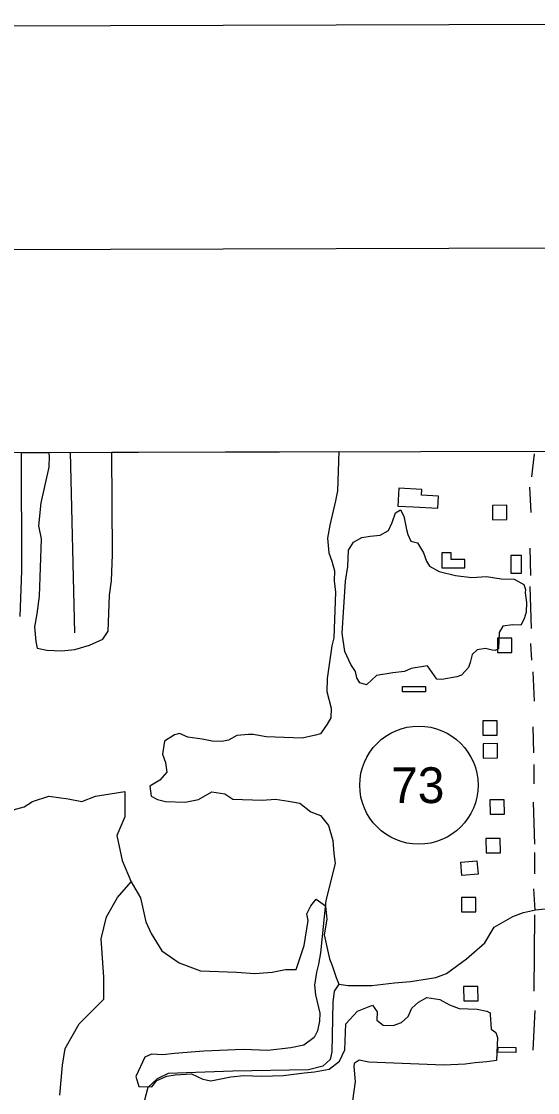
# Model space of a CAD drawing. Extents: x 3355677 to 3393573, y 612928 to 638357.
# Drawn here: x 3388107 to 3389547, y 634782 to 637774 of the extents above; entities that cross this region are included whole.
import ezdxf

# ---------------------------------------------------------------- set-up
doc = ezdxf.new("R2010")
doc.units = 0
for name, color, linetype in [('G-ANNO-NPLT', 7, 'Continuous'), ('V-ANNO-SYMB', 7, 'Continuous'), ('V-BLDG-OTLN', 7, 'Continuous'), ('V-GRID-FRAM', 7, 'Continuous'), ('V-ROAD-IDEN', 7, 'Continuous'), ('V-SITE-VEGE', 7, 'Continuous'), ('V-TOPO-SHOR', 7, 'Continuous')]:
    doc.layers.add(name, color=color, linetype=linetype)

msp = doc.modelspace()

# ---------------------------------------------------------------- linework, layer by layer
at = {"layer": 'G-ANNO-NPLT'}
msp.add_lwpolyline([(3356323.2, 613511.2), (3392989.8, 613607.2), (3392926.5, 637773.8), (3356260, 637677.8)], close=True, dxfattribs=at)
at = {"layer": 'V-ANNO-SYMB'}
msp.add_lwpolyline([(3359071.7, 614143.5), (3392154.8, 614230.1), (3392094.8, 637146.6), (3359011.7, 637060), (3359071.7, 614143.5)], dxfattribs=at)
at = {"layer": 'V-BLDG-OTLN'}
for points in [[(3389200.9, 636417.8), (3389268.8, 636414), (3389270.7, 636448), (3389223.3, 636450.7), (3389224.2, 636466.6), (3389159.9, 636470.1), (3389157.1, 636420.2)], [(3389461.6, 636382.4), (3389461.1, 636422.4), (3389421.1, 636421.9), (3389421.6, 636381.9)], [(3389280.1, 636289.5), (3389280.1, 636248.1), (3389344.3, 636248.1), (3389344.3, 636270.7), (3389306.5, 636270.7), (3389306.5, 636289.5)], [(3389472.5, 636282), (3389472.5, 636233), (3389502.7, 636233), (3389502.7, 636282)], [(3389475.6, 636011.3), (3389475.1, 636051.3), (3389435.1, 636050.8), (3389435.6, 636010.8)], [(3389170.8, 635916.2), (3389234.9, 635916.2), (3389234.9, 635901.1), (3389170.8, 635901.1)], [(3389434.9, 635780.4), (3389434.4, 635820.4), (3389394.4, 635819.9), (3389394.9, 635779.9)], [(3389435.6, 635716.6), (3389435.1, 635756.6), (3389395.1, 635756.1), (3389395.6, 635716.1)], [(3389454.7, 635559.9), (3389454.2, 635599.9), (3389414.2, 635599.4), (3389414.7, 635559.4)], [(3389443.5, 635452.1), (3389443, 635492.1), (3389403, 635491.6), (3389403.5, 635451.6)], [(3389332.9, 635425.9), (3389378.2, 635429.7), (3389381.3, 635392.5), (3389336, 635388.8)], [(3389375.1, 635287.1), (3389374.6, 635327), (3389334.6, 635326.5), (3389335.1, 635286.5)], [(3389381.1, 635038.4), (3389380.6, 635078.4), (3389340.6, 635077.9), (3389341.1, 635037.9)], [(3389486.7, 634894.3), (3389436.7, 634895), (3389436.9, 634909), (3389486.9, 634908.3)]]:
    msp.add_lwpolyline(points, close=True, dxfattribs=at)
at = {"layer": 'V-GRID-FRAM'}
msp.add_lwpolyline([(3359767.9, 636495.9), (3391341.6, 636578.5), (3391397.2, 618394.8), (3359807.6, 618312.1), (3359767.9, 636495.9)], dxfattribs=at)
at = {"layer": 'V-ROAD-IDEN'}
msp.add_circle((3389216.1, 635640.6), 165, dxfattribs=at)
at = {"layer": 'V-SITE-VEGE'}
for p, q in [((3388107.6, 636570.1), (3388182.9, 636570.2)), ((3388108.7, 636239.2), (3388107.6, 636570.1)), ((3388182.9, 636570.2), (3388184.5, 636560.4)), ((3388184.5, 636560.4), (3388183.3, 636528.5)), ((3388359.4, 636570.7), (3388993.2, 636572.4)), ((3388361.5, 636284.7), (3388359.4, 636570.7)), ((3388993.2, 636572.4), (3388989.1, 636462.3)), ((3388183.3, 636528.5), (3388161.3, 636428.9)), ((3388983.6, 636435.1), (3388967.4, 636367.3)), ((3388989.1, 636462.3), (3388983.6, 636435.1)), ((3388161.3, 636428.9), (3388154.4, 636365.3)), ((3388154.4, 636365.3), (3388162.2, 636328.5)), ((3388967.4, 636367.3), (3388961.5, 636331)), ((3388162.2, 636328.5), (3388156.3, 636169)), ((3388961.5, 636331), (3388964.5, 636289.8)), ((3388358.8, 636211.8), (3388361.5, 636284.7)), ((3388964.5, 636289.8), (3388972.8, 636266.7)), ((3388972.8, 636266.7), (3388980.9, 636239)), ((3388104, 636111.6), (3388108.7, 636239.2)), ((3388980.9, 636239), (3388979.9, 636211.7)), ((3388352.8, 636170.9), (3388358.8, 636211.8)), ((3388979.9, 636211.7), (3388983.3, 636179.6)), ((3388156.3, 636169), (3388149.9, 636119.1)), ((3388349.1, 636070.7), (3388352.8, 636170.9)), ((3388983.3, 636179.6), (3388978.6, 636052)), ((3388149.9, 636119.1), (3388144, 636082.8)), ((3388144, 636082.8), (3388147.1, 636041.6)), ((3388297.4, 636031.5), (3388334.5, 636048.4)), ((3388334.5, 636048.4), (3388349.1, 636070.7)), ((3388978.6, 636052), (3388973.2, 636029.4)), ((3388147.1, 636041.6), (3388151, 636023.2)), ((3388151, 636023.2), (3388178.1, 636017.7)), ((3388178.1, 636017.7), (3388219.2, 636016.1)), ((3388219.2, 636016.1), (3388255.8, 636019.4)), ((3388255.8, 636019.4), (3388297.4, 636031.5)), ((3388973.2, 636029.4), (3388960.7, 635938.6)), ((3388960.7, 635938.6), (3388959.3, 635902.2)), ((3388959.3, 635902.2), (3388971.3, 635856.1)), ((3388971.3, 635856.1), (3388970.3, 635828.7)), ((3388960.5, 635810.9), (3388941.3, 635784.2)), ((3388970.3, 635828.7), (3388960.5, 635810.9)), ((3388534.7, 635780.9), (3388506.7, 635763.7)), ((3388548.6, 635785), (3388534.7, 635780.9)), ((3388571.1, 635775), (3388548.6, 635785)), ((3388708.2, 635779.1), (3388684.9, 635766.3)), ((3388740.3, 635782.5), (3388708.2, 635779.1)), ((3388754, 635782), (3388740.3, 635782.5)), ((3388790.3, 635776.1), (3388754, 635782)), ((3388890.6, 635772.4), (3388790.3, 635776.1)), ((3388927.4, 635780.1), (3388890.6, 635772.4)), ((3388941.3, 635784.2), (3388927.4, 635780.1)), ((3388506.7, 635763.7), (3388500.8, 635727.4)), ((3388611.9, 635769), (3388571.1, 635775)), ((3388639.1, 635763.4), (3388611.9, 635769)), ((3388666.5, 635762.4), (3388639.1, 635763.4)), ((3388684.9, 635766.3), (3388666.5, 635762.4)), ((3388500.8, 635727.4), (3388509.1, 635704.3)), ((3388509.1, 635704.3), (3388512.6, 635676.8)), ((3388512.6, 635676.8), (3388493.6, 635654.7)), ((3388493.6, 635654.7), (3388465.5, 635637.5)), ((3388465.5, 635637.5), (3388469.1, 635610)), ((3388469.1, 635610), (3388487, 635600.2)), ((3388487, 635600.2), (3388509.6, 635594.8)), ((3388564.3, 635592.8), (3388601.2, 635600.5)), ((3388601.2, 635600.5), (3388638.5, 635622)), ((3388638.5, 635622), (3388674.8, 635616.1)), ((3388674.8, 635616.1), (3388697.1, 635601.6)), ((3388697.1, 635601.6), (3388779.2, 635598.5)), ((3388779.2, 635598.5), (3388815.8, 635601.7)), ((3388815.8, 635601.7), (3388852.1, 635595.8)), ((3388509.6, 635594.8), (3388564.3, 635592.8)), ((3388852.1, 635595.8), (3388883.9, 635590.1)), ((3388883.9, 635590.1), (3388915, 635566.2)), ((3388915, 635566.2), (3388942, 635556)), ((3388942, 635556), (3388963.8, 635527.9)), ((3388963.8, 635527.9), (3388976, 635486.3)), ((3388976, 635486.3), (3388979.2, 635449.7)), ((3388979.2, 635449.7), (3388982.7, 635422.2)), ((3388982.7, 635422.2), (3388956.1, 635318.3)), ((3388956.1, 635318.3), (3388941.6, 635172.8)), ((3388941.6, 635172.8), (3388935.8, 635141.1)), ((3388930.4, 635118.4), (3388924.5, 635082.2)), ((3388935.8, 635141.1), (3388930.4, 635118.4)), ((3388924.5, 635082.2), (3388928.1, 635054.7)), ((3388928.1, 635054.7), (3388939.9, 635004)), ((3389196.1, 635017.4), (3389215.1, 635034.9)), ((3389215.1, 635034.9), (3389238.4, 635047.8)), ((3389238.4, 635047.8), (3389274.7, 635041.9)), ((3389274.7, 635041.9), (3389301.5, 635027.2)), ((3388939.9, 635004), (3388939.1, 634981.2)), ((3389011.9, 634974), (3389045.2, 635009.3)), ((3389045.2, 635009.3), (3389086.9, 635026)), ((3389086.9, 635026), (3389099.9, 635007.3)), ((3389099.9, 635007.3), (3389099, 634984.5)), ((3389186.2, 634994.9), (3389196.1, 635017.4)), ((3389301.5, 635027.2), (3389328.6, 635017.1)), ((3389328.6, 635017.1), (3389378.7, 635015.2)), ((3389378.7, 635015.2), (3389405.9, 635009.7)), ((3389405.9, 635009.7), (3389414.9, 635004.8)), ((3389414.9, 635004.8), (3389414.7, 635000.2)), ((3389414.7, 635000.2), (3389417.8, 634959)), ((3388939.1, 634981.2), (3388933.5, 634954.1)), ((3389009.2, 634901.1), (3389011.9, 634974)), ((3389099, 634984.5), (3389116.8, 634970.1)), ((3389116.8, 634970.1), (3389144.1, 634969.1)), ((3389144.1, 634969.1), (3389167.3, 634977.4)), ((3389167.3, 634977.4), (3389186.2, 634994.9)), ((3388933.5, 634954.1), (3388923.7, 634936.2)), ((3389417.8, 634959), (3389431.1, 634949.4)), ((3389431.1, 634949.4), (3389435.2, 634935.6)), ((3388895.5, 634914.4), (3388858.7, 634906.6)), ((3388923.7, 634936.2), (3388895.5, 634914.4)), ((3389435.2, 634935.6), (3389432.8, 634871.8)), ((3388451.3, 634880.6), (3388426.5, 634826.8)), ((3388469.9, 634889), (3388451.3, 634880.6)), ((3388501.8, 634887.9), (3388469.9, 634889)), ((3388533.9, 634891.2), (3388501.8, 634887.9)), ((3388616.3, 634897.3), (3388533.9, 634891.2)), ((3388726.1, 634902.4), (3388616.3, 634897.3)), ((3388794.5, 634899.9), (3388726.1, 634902.4)), ((3388858.7, 634906.6), (3388794.5, 634899.9)), ((3388994.3, 634869.7), (3389009.2, 634901.1)), ((3388966.1, 634847.9), (3388994.3, 634869.7)), ((3389035.2, 634863.6), (3389034.9, 634854.5)), ((3389034.9, 634854.5), (3389037.9, 634813.3)), ((3389049.2, 634872.2), (3389035.2, 634863.6)), ((3389076.4, 634866.7), (3389049.2, 634872.2)), ((3389286.2, 634858.9), (3389076.4, 634866.7)), ((3389345.7, 634861.3), (3389286.2, 634858.9)), ((3389373.2, 634864.9), (3389345.7, 634861.3)), ((3389405.3, 634868.2), (3389373.2, 634864.9)), ((3389432.8, 634871.8), (3389405.3, 634868.2)), ((3388426.5, 634826.8), (3388434.6, 634799.1)), ((3388485.4, 634815.5), (3388513.3, 634828.1)), ((3388513.3, 634828.1), (3388536.3, 634831.8)), ((3388536.3, 634831.8), (3388582.1, 634834.7)), ((3388582.1, 634834.7), (3388613.5, 634819.9)), ((3388613.5, 634819.9), (3388636.1, 634814.5)), ((3388636.1, 634814.5), (3388691.3, 634826.1)), ((3388691.3, 634826.1), (3388728, 634829.3)), ((3388728, 634829.3), (3388778.1, 634827.5)), ((3388778.1, 634827.5), (3388837.6, 634829.9)), ((3388837.6, 634829.9), (3388897.2, 634836.8)), ((3388897.2, 634836.8), (3388924.8, 634840.3)), ((3388924.8, 634840.3), (3388966.1, 634847.9)), ((3388434.6, 634799.1), (3388471.1, 634797.7)), ((3388471.1, 634797.7), (3388485.4, 634815.5)), ((3389037.9, 634813.3), (3389031.3, 634758.8))]:
    msp.add_line(p, q, dxfattribs=at)
msp.add_lwpolyline([(3389001.9, 636064.8), (3389011.8, 636210.5), (3389017.9, 636251.3), (3389019.6, 636296.9), (3389034.1, 636319.2), (3389057.4, 636332), (3389080.4, 636335.7), (3389107.9, 636339.3), (3389131.2, 636352.1), (3389141.2, 636374.5), (3389151.3, 636401.5), (3389165.3, 636410.1), (3389173.8, 636391.6), (3389181.5, 636354.8), (3389185.6, 636341), (3389194, 636322.4), (3389212.1, 636317.2), (3389229.3, 636289.2), (3389237.6, 636266), (3389246.2, 636252), (3389273.1, 636237.3), (3389318.4, 636226.6), (3389363.8, 636220.3), (3389405, 636223.4), (3389445.9, 636217.3), (3389482.4, 636215.9), (3389509.2, 636201.3), (3389513.3, 636187.4), (3389513, 636178.3), (3389516.5, 636150.8), (3389515.5, 636123.5), (3389510.3, 636105.4), (3389500.5, 636087.5), (3389477.7, 636088.4), (3389450.1, 636084.8), (3389440.3, 636066.9), (3389438.7, 636021.4), (3389429.4, 636017.1), (3389420.3, 636017.5), (3389402.2, 636022.7), (3389379.2, 636019), (3389365, 636005.8), (3389359.6, 635983.2), (3389354.6, 635969.7), (3389335.5, 635947.6), (3389321.6, 635943.6), (3389280.3, 635936), (3389266.6, 635936.5), (3389240.6, 635973.9), (3389194.6, 635966.5), (3389176, 635958), (3389143.9, 635954.7), (3389098, 635947.2), (3389069.6, 635920.9), (3389051.6, 635926.1), (3389042.9, 635940.1), (3389039.1, 635958.5), (3389026, 635977.3), (3389009.1, 636014.4)], close=True, dxfattribs=at)
at = {"layer": 'V-TOPO-SHOR'}
for p, q in [((3388256, 636065.7), (3388244.2, 636570.4)), ((3389531.7, 636502.1), (3389538.7, 636566.3)), ((3389529.8, 636402.5), (3389525.8, 636473.4)), ((3389528.3, 636226), (3389526.2, 636302.7)), ((3389530.6, 636078.3), (3389526.5, 636195.3)), ((3389530.9, 635990), (3389528.8, 636036.1)), ((3389538.8, 635874.9), (3389534.8, 635957.4)), ((3389537.3, 635731.1), (3389535.2, 635804)), ((3389537.5, 635644.7), (3389537.4, 635698.5)), ((3389539.9, 635475.9), (3389535.7, 635592.9)), ((3389540.1, 635393.4), (3389539.9, 635452.9)), ((3389540.4, 635291.8), (3389536.4, 635351.2)), ((3389538.5, 635278.3), (3389537.1, 635065.4)), ((3389539.2, 635011.7), (3389533.7, 634900.4))]:
    msp.add_line(p, q, dxfattribs=at)
for points in [[(3388084.1, 635572), (3388114.7, 635579.7), (3388137.7, 635595), (3388183.7, 635610.3), (3388237.4, 635602.7), (3388275.7, 635595), (3388314.1, 635610.3), (3388395.3, 635622.9)], [(3388395.3, 635622.9), (3388395.3, 635552.4), (3388373, 635500.5), (3388387.9, 635430), (3388413.8, 635370.6), (3388439.8, 635326.1), (3388454.6, 635259.4), (3388469.5, 635226), (3388499.1, 635177.7), (3388547.4, 635144.4), (3388606.7, 635122.1), (3388706.9, 635118.4), (3388758.8, 635114.7), (3388807, 635118.4), (3388844.1, 635125.8), (3388859, 635125.8), (3388873.8, 635125.8), (3388896.1, 635192.6), (3388907.2, 635263.1), (3388903.5, 635281.6), (3388914.6, 635303.9), (3388929.5, 635322.4), (3388955.4, 635303.9), (3388959.1, 635266.8), (3388951.7, 635222.3), (3388966.5, 635155.5), (3388974, 635136.9), (3388985.1, 635103.6), (3388992.5, 635085), (3389018.5, 635081.3), (3389085.3, 635081.3), (3389148.3, 635088.7), (3389192.8, 635092.4), (3389263.3, 635103.6), (3389293, 635114.7), (3389348.6, 635155.5), (3389400.6, 635200), (3389426.5, 635244.5), (3389478.5, 635274.2), (3389508.1, 635285.3), (3389541.5, 635292.7), (3389649.1, 635303.9)], [(3388214.4, 634774.6), (3388222.1, 634858.9), (3388229.7, 634904.9), (3388268.1, 634973.9), (3388283.4, 634989.3), (3388337.1, 635042.9), (3388337.1, 635104.3), (3388329.4, 635211.6), (3388344.8, 635272.9), (3388375.4, 635326.6), (3388375.4, 635326.6), (3388413.8, 635370.6)], [(3388992.5, 635085), (3388979.7, 635065.1), (3388976.5, 635034.5), (3388973.7, 634895.9), (3388968.9, 634874.9), (3388948, 634855.5), (3388907.8, 634845.8), (3388696.7, 634842), (3388516.2, 634835.1), (3388485.6, 634820.5), (3388459.9, 634796.2), (3388450.3, 634760.8), (3388429.6, 634696.3), (3388426.4, 634654.3), (3388426.6, 634602.8), (3388423.4, 634577), (3388409, 634548), (3388376.8, 634518.9), (3388480.6, 634272.6), (3388547.1, 634114.8), (3388587.7, 633994.1), (3388618.7, 633866.9), (3388636.7, 633759)]]:
    msp.add_lwpolyline(points, dxfattribs=at)

# ---------------------------------------------------------------- texts
at = {"layer": 'V-ROAD-IDEN'}
msp.add_text('73', height=100, dxfattribs=at).set_placement((3389138.6, 635590.6))

doc.saveas('drawing.dxf')
